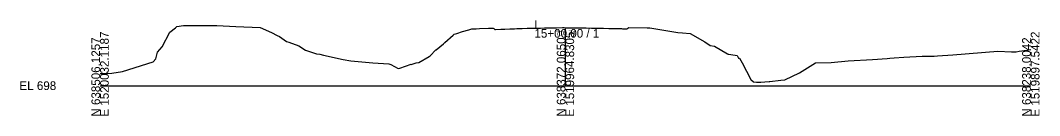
# Model space of a CAD drawing. Extents: x -26 to 3903, y -10 to 9531.
# Drawn here: x -25.7 to 302.8, y 4990.3 to 5021.1 of the extents above; entities that cross this region are included whole.
import ezdxf

# ---------------------------------------------------------------- set-up
doc = ezdxf.new("R2010")
doc.units = 0
for name, color, linetype in [('Default', 7, 'Continuous'), ('Exist Cross Section Cell', 7, 'Continuous'), ('Exist XS Center Line Elevation Label', 7, 'Continuous'), ('Exist XS Ground Line', 7, 'Continuous')]:
    doc.layers.add(name, color=color, linetype=linetype)

msp = doc.modelspace()

# ---------------------------------------------------------------- linework, layer by layer
at = {"layer": 'Exist Cross Section Cell'}
for p, q in [((150, 5000), (150, 5018.32)), ((0, 5000), (150, 5000)), ((150, 5000), (300, 5000))]:
    msp.add_line(p, q, dxfattribs=at)
at = {"layer": 'Exist XS Ground Line'}
msp.add_lwpolyline([(0, 5003.92), (2.24, 5003.9), (3.77, 5004.02), (7.21, 5004.62), (17.15, 5007.75), (18.01, 5008.64), (18.49, 5010.79), (20.04, 5012.55), (22.46, 5017.25), (24.28, 5018.68), (24.42, 5018.84), (24.78, 5019.13), (26.86, 5019.42), (29.34, 5019.48), (33.01, 5019.43), (37.59, 5019.43), (43.76, 5019.09), (51.55, 5018.78), (55.21, 5017.23), (57.12, 5016.23), (57.82, 5015.87), (60.1, 5014.25), (60.89, 5014.04), (64.02, 5012.88), (66.21, 5011.52), (68.51, 5010.7), (69.71, 5010.32), (70.78, 5010.17), (71.98, 5009.87), (78.37, 5008.5), (80.77, 5008.04), (83.15, 5007.8), (87.95, 5007.41), (93.04, 5007.04), (93.7, 5006.88), (96.06, 5005.59), (96.65, 5005.71), (100.26, 5006.91), (100.4, 5006.81), (100.95, 5007.02), (101.85, 5007.39), (102.75, 5007.44), (106.04, 5009.48), (106.39, 5009.68), (108.24, 5011.58), (108.31, 5011.62), (110.69, 5013.55), (110.96, 5013.76), (111.13, 5013.98), (113.82, 5016.33), (114.15, 5016.61), (115.01, 5016.91), (116.77, 5017.5), (118.84, 5018.09), (119.8, 5018.36), (121.25, 5018.41), (122.33, 5018.44), (125.25, 5018.55), (126.65, 5018.6), (126.87, 5018.44), (127.25, 5018.16), (127.43, 5018.17), (129.16, 5018.26), (130.1, 5018.28), (130.45, 5018.29), (132.06, 5018.35), (133.21, 5018.39), (133.59, 5018.4), (134.36, 5018.43), (135.46, 5018.47), (136.02, 5018.49), (137.66, 5018.54), (138.81, 5018.57), (139.95, 5018.59), (141.04, 5018.61), (141.59, 5018.63), (143.26, 5018.67), (144.38, 5018.69), (145.5, 5018.71), (147.16, 5018.73), (149.01, 5018.75), (149.63, 5018.76), (150.01, 5018.74), (151.06, 5018.73), (152.23, 5018.73), (152.79, 5018.72), (154.09, 5018.71), (155.58, 5018.69), (156.67, 5018.67), (158.37, 5018.63), (159.79, 5018.62), (159.95, 5018.62), (160.6, 5018.61), (161.15, 5018.59), (161.52, 5018.58), (162.24, 5018.57), (163.96, 5018.52), (165.72, 5018.47), (166.73, 5018.44), (167.99, 5018.43), (168.05, 5018.43), (168.06, 5018.43), (168.07, 5018.43), (168.42, 5018.41), (169.74, 5018.34), (169.77, 5018.36), (170.46, 5018.81), (176.3, 5018.74), (176.68, 5018.73), (177.15, 5018.65), (186.19, 5017.19), (187.75, 5017.11), (190.15, 5016.86), (194.9, 5014.13), (196.67, 5013.01), (198.08, 5012.73), (202.28, 5010.28), (202.41, 5010.19), (202.48, 5010.13), (202.71, 5010.14), (203.26, 5010.06), (205.3, 5009.78), (205.78, 5008.87), (206.06, 5008.9), (206.97, 5007.43), (209.8, 5001.98), (210.64, 5001.29), (210.67, 5001.26), (211.54, 5001.11), (211.56, 5001.11), (212.84, 5001.16), (212.96, 5001.16), (214.32, 5001.26), (215.71, 5001.37), (215.89, 5001.38), (219.44, 5001.75), (220.67, 5001.84), (225.49, 5004.17), (230.63, 5007.42), (235.69, 5007.52), (241.17, 5008.01), (248.92, 5008.41), (253.66, 5008.77), (254.53, 5008.85), (256.01, 5008.96), (259.08, 5009.17), (265.03, 5009.56), (266.09, 5009.56), (268.9, 5009.59), (269.92, 5009.6), (274.87, 5009.97), (289.32, 5011.12), (293.81, 5010.99), (295.3, 5010.94), (296.25, 5011.11), (298.75, 5011.52), (300, 5011.64)], dxfattribs=at)

# ---------------------------------------------------------------- texts
at = {"layer": 'Default'}
msp.add_text('-', height=0.0001, dxfattribs=at).set_placement((0, 5000))
at = {"layer": 'Exist Cross Section Cell'}
for s, p in [('L', (140, 5018.32)), ('15+00.00 / 1', (140, 5015.52)), ('EL 698', (-26, 4998.6))]:
    msp.add_text(s, height=2.8, dxfattribs=at).set_placement(p)
for s, p in [('E 1520032.1187', (2.8, 4990)), ('E 1519964.8305', (152.8, 4990)), ('E 1519897.5422', (302.8, 4990)), ('N 638506.1257', (0, 4990)), ('N 638372.0650', (150, 4990)), ('N 638238.0042', (300, 4990))]:
    msp.add_text(s, height=2.8, rotation=90, dxfattribs=at).set_placement(p)
at = {"layer": 'Exist XS Center Line Elevation Label'}
msp.add_text('716.74', height=1.5, rotation=0.8401, dxfattribs=at).set_placement((146.92, 5016.24))

doc.saveas('drawing.dxf')
